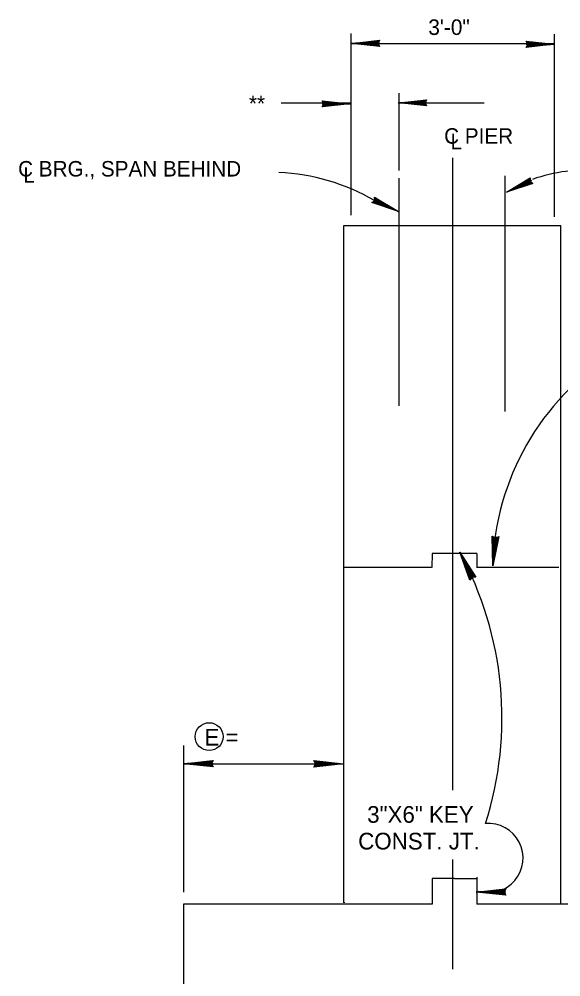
# Model space of a CAD drawing. Extents: x 1.6 to 6.29, y 2.8 to 7.08.
# Drawn here: x 3.826 to 4.232, y 5.231 to 5.949 of the extents above; entities that cross this region are included whole.
import ezdxf

# ---------------------------------------------------------------- set-up
doc = ezdxf.new("R2010")
doc.units = 0
doc.layers.add('Level 1', color=7, linetype='Continuous')
doc.layers.add('Level 5', color=7, linetype='Continuous')

msp = doc.modelspace()

# ---------------------------------------------------------------- linework, layer by layer
at = {"layer": 'Level 1'}
for p, q in [((4.07433, 5.93775), (4.07433, 5.80192)), ((4.07508, 5.93042), (4.09575, 5.93275)), ((4.09533, 5.93242), (4.081, 5.93083)), ((4.09533, 5.93217), (4.081, 5.93067)), ((4.09542, 5.932), (4.081, 5.93042)), ((4.09542, 5.93175), (4.081, 5.93017)), ((4.08408, 5.93017), (4.09475, 5.93142)), ((4.09475, 5.93142), (4.09433, 5.93017)), ((4.0945, 5.9305), (4.09483, 5.93142)), ((4.09575, 5.93275), (4.09475, 5.93042)), ((4.09483, 5.93142), (4.09533, 5.93242)), ((4.20567, 5.93208), (4.2265, 5.92983)), ((4.20675, 5.92983), (4.20567, 5.93208)), ((4.206, 5.93175), (4.22158, 5.93)), ((4.206, 5.93167), (4.22158, 5.92992)), ((4.206, 5.93158), (4.22158, 5.92992)), ((4.206, 5.93142), (4.22158, 5.92967)), ((4.20608, 5.93183), (4.22158, 5.93017)), ((4.20717, 5.92992), (4.20625, 5.93142)), ((4.20625, 5.93142), (4.20667, 5.93117)), ((4.22658, 5.93725), (4.22658, 5.80067)), ((4.0745, 5.93042), (4.2265, 5.93042)), ((4.09575, 5.93042), (4.07508, 5.93042)), ((4.09575, 5.92817), (4.07508, 5.93042)), ((4.08042, 5.93083), (4.07792, 5.93058)), ((4.07792, 5.93058), (4.09442, 5.93067)), ((4.0785, 5.93025), (4.08042, 5.93083)), ((4.08775, 5.92992), (4.0785, 5.93025)), ((4.09542, 5.92892), (4.08, 5.9305)), ((4.09533, 5.92867), (4.08, 5.93033)), ((4.09533, 5.92842), (4.08, 5.93017)), ((4.09533, 5.92842), (4.08, 5.93017)), ((4.09533, 5.92858), (4.08, 5.93017)), ((4.09467, 5.93092), (4.08408, 5.93017)), ((4.08517, 5.93), (4.08517, 5.93025)), ((4.08517, 5.93025), (4.087, 5.93017)), ((4.09442, 5.93017), (4.08517, 5.93)), ((4.087, 5.93017), (4.09442, 5.93)), ((4.09475, 5.92933), (4.08775, 5.92992)), ((4.09442, 5.93), (4.0885, 5.92992)), ((4.0885, 5.92992), (4.09467, 5.92967)), ((4.09442, 5.93067), (4.0895, 5.93092)), ((4.0895, 5.93092), (4.09467, 5.93092)), ((4.09467, 5.92967), (4.09025, 5.92958)), ((4.09025, 5.92958), (4.09475, 5.92933)), ((4.09433, 5.92992), (4.09375, 5.92967)), ((4.09375, 5.92967), (4.09417, 5.929)), ((4.09417, 5.929), (4.0945, 5.9305)), ((4.09433, 5.93017), (4.09517, 5.92875)), ((4.09475, 5.92908), (4.09433, 5.92992)), ((4.09475, 5.93042), (4.09575, 5.92817)), ((4.09517, 5.92875), (4.09475, 5.92908)), ((4.20567, 5.92983), (4.2265, 5.92983)), ((4.2265, 5.92983), (4.20567, 5.92742)), ((4.20567, 5.92742), (4.20675, 5.92983)), ((4.206, 5.92842), (4.2205, 5.93)), ((4.206, 5.92825), (4.2205, 5.92983)), ((4.206, 5.928), (4.22058, 5.92958)), ((4.20608, 5.92775), (4.22058, 5.92942)), ((4.2065, 5.92892), (4.20608, 5.92783)), ((4.20692, 5.92967), (4.2065, 5.92892)), ((4.21108, 5.93067), (4.20658, 5.93092)), ((4.20658, 5.93092), (4.21375, 5.93033)), ((4.20667, 5.93117), (4.20717, 5.93033)), ((4.21733, 5.92992), (4.20667, 5.92892)), ((4.20667, 5.92892), (4.20717, 5.92992)), ((4.20683, 5.9305), (4.21108, 5.93067)), ((4.21308, 5.93033), (4.20683, 5.9305)), ((4.20683, 5.92925), (4.21733, 5.92992)), ((4.21192, 5.92925), (4.20683, 5.92925)), ((4.20725, 5.93117), (4.20692, 5.92967)), ((4.207, 5.93017), (4.21308, 5.93033)), ((4.207, 5.93), (4.21633, 5.93017)), ((4.2145, 5.93), (4.207, 5.93017)), ((4.22375, 5.92967), (4.207, 5.92958)), ((4.207, 5.92958), (4.21192, 5.92925)), ((4.20717, 5.93033), (4.20758, 5.93058)), ((4.20758, 5.93058), (4.20725, 5.93117)), ((4.21375, 5.93033), (4.223, 5.92992)), ((4.21625, 5.92992), (4.2145, 5.93)), ((4.21633, 5.93017), (4.21625, 5.92992)), ((4.223, 5.92992), (4.22108, 5.92942)), ((4.22108, 5.92942), (4.22375, 5.92967)), ((4.11025, 5.89317), (4.11025, 5.83517)), ((4.02225, 5.88583), (4.07375, 5.88583)), ((4.05292, 5.8875), (4.07375, 5.88525)), ((4.054, 5.88525), (4.05292, 5.8875)), ((4.05292, 5.88525), (4.07375, 5.88525)), ((4.07375, 5.88525), (4.05292, 5.88283)), ((4.05292, 5.88283), (4.054, 5.88525)), ((4.05325, 5.88717), (4.06883, 5.88542)), ((4.05325, 5.88708), (4.06883, 5.88533)), ((4.05325, 5.887), (4.06883, 5.88533)), ((4.05325, 5.88683), (4.06883, 5.88508)), ((4.05325, 5.88383), (4.06775, 5.88542)), ((4.05325, 5.88367), (4.06775, 5.88525)), ((4.05325, 5.88342), (4.06783, 5.885)), ((4.05333, 5.88725), (4.06883, 5.88558)), ((4.05333, 5.88317), (4.06783, 5.88483)), ((4.05375, 5.88433), (4.05333, 5.88325)), ((4.05442, 5.88533), (4.0535, 5.88683)), ((4.0535, 5.88683), (4.05392, 5.88658)), ((4.05417, 5.88508), (4.05375, 5.88433)), ((4.05833, 5.88608), (4.05383, 5.88633)), ((4.05383, 5.88633), (4.061, 5.88575)), ((4.05392, 5.88658), (4.05442, 5.88575)), ((4.06458, 5.88533), (4.05392, 5.88433)), ((4.05392, 5.88433), (4.05442, 5.88533)), ((4.05408, 5.88592), (4.05833, 5.88608)), ((4.06033, 5.88575), (4.05408, 5.88592)), ((4.05408, 5.88467), (4.06458, 5.88533)), ((4.05917, 5.88467), (4.05408, 5.88467)), ((4.0545, 5.88658), (4.05417, 5.88508)), ((4.05425, 5.88558), (4.06033, 5.88575)), ((4.05425, 5.88542), (4.06358, 5.88558)), ((4.06175, 5.88542), (4.05425, 5.88558)), ((4.071, 5.88508), (4.05425, 5.885)), ((4.05425, 5.885), (4.05917, 5.88467)), ((4.05442, 5.88575), (4.05483, 5.886)), ((4.05483, 5.886), (4.0545, 5.88658)), ((4.061, 5.88575), (4.07025, 5.88533)), ((4.0635, 5.88533), (4.06175, 5.88542)), ((4.06358, 5.88558), (4.0635, 5.88533)), ((4.07025, 5.88533), (4.06833, 5.88483)), ((4.06833, 5.88483), (4.071, 5.88508)), ((4.10967, 5.88583), (4.17425, 5.88583)), ((4.11025, 5.88583), (4.13092, 5.88817)), ((4.13092, 5.88583), (4.11025, 5.88583)), ((4.13092, 5.88358), (4.11025, 5.88583)), ((4.11558, 5.88625), (4.11308, 5.886)), ((4.11308, 5.886), (4.12958, 5.88608)), ((4.11367, 5.88567), (4.11558, 5.88625)), ((4.12292, 5.88533), (4.11367, 5.88567)), ((4.13058, 5.88433), (4.11517, 5.88592)), ((4.1305, 5.88408), (4.11517, 5.88575)), ((4.1305, 5.88383), (4.11517, 5.88558)), ((4.1305, 5.88383), (4.11517, 5.88558)), ((4.1305, 5.884), (4.11517, 5.88558)), ((4.1305, 5.88783), (4.11617, 5.88625)), ((4.1305, 5.88758), (4.11617, 5.88608)), ((4.13058, 5.88742), (4.11617, 5.88583)), ((4.13058, 5.88717), (4.11617, 5.88558)), ((4.11925, 5.88558), (4.12992, 5.88683)), ((4.12983, 5.88633), (4.11925, 5.88558)), ((4.12033, 5.88542), (4.12033, 5.88567)), ((4.12033, 5.88567), (4.12217, 5.88558)), ((4.12958, 5.88558), (4.12033, 5.88542)), ((4.12217, 5.88558), (4.12958, 5.88542)), ((4.12992, 5.88475), (4.12292, 5.88533)), ((4.12958, 5.88542), (4.12367, 5.88533)), ((4.12367, 5.88533), (4.12983, 5.88508)), ((4.12958, 5.88608), (4.12467, 5.88633)), ((4.12467, 5.88633), (4.12983, 5.88633)), ((4.12983, 5.88508), (4.12542, 5.885)), ((4.12542, 5.885), (4.12992, 5.88475)), ((4.1295, 5.88533), (4.12892, 5.88508)), ((4.12892, 5.88508), (4.12933, 5.88442)), ((4.12933, 5.88442), (4.12967, 5.88592)), ((4.12992, 5.88683), (4.1295, 5.88558)), ((4.1295, 5.88558), (4.13033, 5.88417)), ((4.12992, 5.8845), (4.1295, 5.88533)), ((4.12967, 5.88592), (4.13, 5.88683)), ((4.13092, 5.88817), (4.12992, 5.88583)), ((4.12992, 5.88583), (4.13092, 5.88358)), ((4.13033, 5.88417), (4.12992, 5.8845)), ((4.13, 5.88683), (4.1305, 5.88783)), ((4.1895, 5.83133), (4.1895, 5.65483)), ((4.11033, 5.8295), (4.11033, 5.65892)), ((4.19075, 5.81892), (4.2085, 5.82983)), ((4.2095, 5.82767), (4.19075, 5.81892)), ((4.2105, 5.82558), (4.19075, 5.81892)), ((4.19325, 5.82033), (4.20817, 5.82733)), ((4.2025, 5.82392), (4.19392, 5.82033)), ((4.20983, 5.82617), (4.19525, 5.82117)), ((4.21, 5.82592), (4.19525, 5.82083)), ((4.20983, 5.82583), (4.19525, 5.82092)), ((4.20983, 5.82575), (4.19525, 5.82083)), ((4.21, 5.82567), (4.19533, 5.82075)), ((4.20825, 5.82925), (4.19592, 5.82183)), ((4.20842, 5.82917), (4.196, 5.82158)), ((4.2085, 5.82892), (4.19608, 5.82142)), ((4.20858, 5.82867), (4.19625, 5.82117)), ((4.199, 5.8225), (4.20817, 5.82808)), ((4.20825, 5.82775), (4.199, 5.8225)), ((4.20825, 5.827), (4.2, 5.82292)), ((4.20158, 5.82375), (4.20842, 5.82675)), ((4.20917, 5.82642), (4.2025, 5.82392)), ((4.20842, 5.82675), (4.20317, 5.82408)), ((4.20317, 5.82408), (4.20875, 5.82658)), ((4.20358, 5.82558), (4.20825, 5.82775)), ((4.20817, 5.82733), (4.20358, 5.82558)), ((4.20875, 5.82658), (4.20483, 5.82458)), ((4.20483, 5.82458), (4.20917, 5.82642)), ((4.20842, 5.8265), (4.20808, 5.82617)), ((4.20808, 5.82617), (4.20875, 5.82575)), ((4.20817, 5.82808), (4.20825, 5.82683)), ((4.20825, 5.82817), (4.20825, 5.82925)), ((4.20825, 5.82717), (4.20825, 5.82817)), ((4.20875, 5.82575), (4.20825, 5.82717)), ((4.20825, 5.82683), (4.20967, 5.82592)), ((4.20908, 5.82592), (4.20842, 5.8265)), ((4.2085, 5.82983), (4.2085, 5.82717)), ((4.2085, 5.82717), (4.2105, 5.82558)), ((4.20967, 5.82592), (4.20908, 5.82592)), ((4.1955, 5.8215), (4.19325, 5.82033)), ((4.19392, 5.82033), (4.1955, 5.8215)), ((4.2, 5.823), (4.20158, 5.82375)), ((4.2, 5.82292), (4.2, 5.823)), ((4.09017, 5.81117), (4.09225, 5.81275)), ((4.11008, 5.80442), (4.09017, 5.81117)), ((4.09158, 5.812), (4.09075, 5.81125)), ((4.09075, 5.81142), (4.10467, 5.80675)), ((4.09075, 5.81117), (4.1045, 5.80658)), ((4.09092, 5.81167), (4.10467, 5.807)), ((4.091, 5.81192), (4.10475, 5.80717)), ((4.09125, 5.81325), (4.11008, 5.80442)), ((4.09225, 5.81267), (4.09158, 5.812)), ((4.09175, 5.812), (4.09258, 5.81275)), ((4.10192, 5.80842), (4.09175, 5.812)), ((4.09667, 5.81017), (4.092, 5.81217)), ((4.092, 5.81217), (4.10192, 5.80842)), ((4.09217, 5.81525), (4.11008, 5.80442)), ((4.09225, 5.81275), (4.09217, 5.81525)), ((4.09225, 5.81467), (4.10567, 5.80658)), ((4.09225, 5.8145), (4.10558, 5.80642)), ((4.09325, 5.81392), (4.09225, 5.81267)), ((4.09233, 5.81492), (4.10575, 5.80667)), ((4.09233, 5.81483), (4.10575, 5.80667)), ((4.09258, 5.81275), (4.09233, 5.8145)), ((4.09233, 5.8145), (4.09267, 5.814)), ((4.1075, 5.8055), (4.09233, 5.81242)), ((4.09233, 5.81242), (4.09667, 5.81017)), ((4.0925, 5.81492), (4.10575, 5.80675)), ((4.0965, 5.81167), (4.0925, 5.81392)), ((4.0925, 5.81392), (4.09875, 5.81025)), ((4.09817, 5.81058), (4.09258, 5.81342)), ((4.09258, 5.81342), (4.0965, 5.81167)), ((4.09258, 5.81283), (4.101, 5.80908)), ((4.09267, 5.814), (4.09275, 5.81308)), ((4.09942, 5.80967), (4.09267, 5.813)), ((4.09267, 5.813), (4.09817, 5.81058)), ((4.09275, 5.81308), (4.09325, 5.81308)), ((4.09325, 5.81308), (4.09325, 5.81392)), ((4.09875, 5.81025), (4.107, 5.80608)), ((4.10092, 5.80892), (4.09942, 5.80967)), ((4.101, 5.80908), (4.10092, 5.80892)), ((4.107, 5.80608), (4.105, 5.80642)), ((4.105, 5.80642), (4.1075, 5.8055)), ((4.06908, 5.28692), (4.06908, 5.79417)), ((4.06908, 5.79417), (4.2315, 5.79417)), ((4.2315, 5.28625), (4.2315, 5.79417)), ((4.18067, 5.53925), (4.18017, 5.5615)), ((4.18017, 5.5615), (4.18258, 5.56008)), ((4.18042, 5.56108), (4.18083, 5.54558)), ((4.1815, 5.5605), (4.1805, 5.56108)), ((4.18258, 5.56125), (4.18067, 5.53925)), ((4.18508, 5.56108), (4.18067, 5.53925)), ((4.18067, 5.561), (4.181, 5.5455)), ((4.18083, 5.54225), (4.18225, 5.55983)), ((4.18092, 5.561), (4.18125, 5.54558)), ((4.18425, 5.56075), (4.18108, 5.5445)), ((4.18117, 5.561), (4.18158, 5.54567)), ((4.18442, 5.56075), (4.18117, 5.5445)), ((4.18458, 5.56067), (4.18142, 5.54442)), ((4.18475, 5.56067), (4.1815, 5.54442)), ((4.18467, 5.56067), (4.1815, 5.54442)), ((4.18242, 5.55992), (4.1815, 5.5605)), ((4.18183, 5.54883), (4.1815, 5.56033)), ((4.1815, 5.56033), (4.18275, 5.55967)), ((4.1815, 5.55475), (4.182, 5.56017)), ((4.18225, 5.55983), (4.1815, 5.55475)), ((4.182, 5.56017), (4.18183, 5.54883)), ((4.18283, 5.55975), (4.182, 5.55)), ((4.18217, 5.55183), (4.18283, 5.55975)), ((4.184, 5.55942), (4.18242, 5.55992)), ((4.18367, 5.56017), (4.1825, 5.55267)), ((4.18258, 5.56008), (4.18508, 5.56108)), ((4.18267, 5.55342), (4.18317, 5.56008)), ((4.18283, 5.55975), (4.18267, 5.55342)), ((4.18275, 5.55967), (4.18433, 5.56058)), ((4.183, 5.55542), (4.18367, 5.56017)), ((4.18317, 5.56008), (4.183, 5.55542)), ((4.184, 5.56008), (4.18308, 5.55967)), ((4.18308, 5.55967), (4.18325, 5.55917)), ((4.18325, 5.55917), (4.184, 5.55942)), ((4.18433, 5.56058), (4.184, 5.56008)), ((4.1825, 5.55267), (4.18108, 5.54292)), ((4.18175, 5.55008), (4.18217, 5.55183)), ((4.13525, 5.54833), (4.135, 5.53783)), ((4.16867, 5.54833), (4.13525, 5.54833)), ((4.16575, 5.5295), (4.15583, 5.54942)), ((4.16333, 5.52842), (4.15583, 5.54942)), ((4.15583, 5.54942), (4.16792, 5.53075)), ((4.15875, 5.5445), (4.15725, 5.54692)), ((4.15725, 5.54692), (4.16508, 5.53108)), ((4.16133, 5.53708), (4.15742, 5.54608)), ((4.15742, 5.54608), (4.15875, 5.5445)), ((4.1635, 5.529), (4.15783, 5.54458)), ((4.16358, 5.52892), (4.15792, 5.54458)), ((4.16367, 5.52892), (4.158, 5.54483)), ((4.16383, 5.529), (4.158, 5.54475)), ((4.16392, 5.52908), (4.15817, 5.54483)), ((4.16867, 5.54833), (4.16867, 5.53775)), ((4.18108, 5.54292), (4.18083, 5.54508)), ((4.18083, 5.54508), (4.18083, 5.54225)), ((4.182, 5.55), (4.18175, 5.55008)), ((4.13483, 5.53792), (4.069, 5.53792)), ((4.16683, 5.5305), (4.15842, 5.54367)), ((4.167, 5.53067), (4.15858, 5.54392)), ((4.16717, 5.53075), (4.15883, 5.54392)), ((4.16733, 5.53083), (4.159, 5.54392)), ((4.1655, 5.53083), (4.16, 5.54058)), ((4.16, 5.54058), (4.16617, 5.53092)), ((4.16025, 5.5395), (4.1605, 5.53967)), ((4.16475, 5.53075), (4.16025, 5.5395)), ((4.1605, 5.53967), (4.16117, 5.53783)), ((4.16117, 5.53783), (4.16458, 5.53058)), ((4.16425, 5.52975), (4.16133, 5.53708)), ((4.23, 5.53792), (4.16858, 5.53792)), ((4.16458, 5.53058), (4.16142, 5.53642)), ((4.16142, 5.53642), (4.1645, 5.53025)), ((4.1645, 5.53025), (4.16233, 5.5345)), ((4.16233, 5.5345), (4.16425, 5.52975)), ((4.16508, 5.53108), (4.16308, 5.53575)), ((4.16308, 5.53575), (4.1655, 5.53083)), ((4.16525, 5.53067), (4.16333, 5.52842)), ((4.164, 5.53108), (4.16358, 5.53042)), ((4.16358, 5.53042), (4.16517, 5.53075)), ((4.16483, 5.53092), (4.16383, 5.52917)), ((4.16383, 5.52917), (4.16392, 5.52992)), ((4.16392, 5.52992), (4.16442, 5.53058)), ((4.16442, 5.53058), (4.164, 5.53108)), ((4.16617, 5.53092), (4.16483, 5.53092)), ((4.16517, 5.53075), (4.16617, 5.53083)), ((4.16792, 5.53075), (4.16525, 5.53067)), ((4.16617, 5.53083), (4.16725, 5.531)), ((3.94908, 5.40475), (3.94908, 5.30458)), ((3.94917, 5.391), (3.97125, 5.3935)), ((3.97125, 5.3935), (3.97008, 5.391)), ((3.97125, 5.391), (3.94917, 5.391)), ((3.97125, 5.38858), (3.94917, 5.391)), ((3.94975, 5.391), (4.066, 5.391)), ((3.95483, 5.39142), (3.95217, 5.39117)), ((3.95217, 5.39117), (3.96975, 5.39125)), ((3.95283, 5.39083), (3.95483, 5.39142)), ((3.96267, 5.39042), (3.95283, 5.39083)), ((3.97075, 5.38892), (3.95433, 5.39075)), ((3.97075, 5.389), (3.95433, 5.39075)), ((3.97075, 5.38883), (3.95433, 5.39067)), ((3.97083, 5.38933), (3.95442, 5.39108)), ((3.97075, 5.38908), (3.95442, 5.39092)), ((3.97075, 5.39308), (3.95542, 5.39142)), ((3.97075, 5.39292), (3.95542, 5.39125)), ((3.97083, 5.39267), (3.9555, 5.391)), ((3.97083, 5.39242), (3.9555, 5.39075)), ((3.95875, 5.39075), (3.97008, 5.392)), ((3.97, 5.39158), (3.95875, 5.39075)), ((3.95992, 5.39058), (3.95992, 5.39083)), ((3.95992, 5.39083), (3.96183, 5.39075)), ((3.96975, 5.39075), (3.95992, 5.39058)), ((3.96183, 5.39075), (3.96975, 5.39058)), ((3.97017, 5.38983), (3.96267, 5.39042)), ((3.96975, 5.39058), (3.96342, 5.39042)), ((3.96342, 5.39042), (3.97, 5.39025)), ((3.96975, 5.39125), (3.96458, 5.39158)), ((3.96458, 5.39158), (3.97, 5.39158)), ((3.97, 5.39025), (3.96533, 5.39008)), ((3.96533, 5.39008), (3.97017, 5.38983)), ((3.96967, 5.39042), (3.96908, 5.39017)), ((3.96908, 5.39017), (3.9695, 5.3895)), ((3.9695, 5.3895), (3.96983, 5.39108)), ((3.97008, 5.392), (3.96967, 5.39075)), ((3.96967, 5.39075), (3.97058, 5.38925)), ((3.97008, 5.38958), (3.96967, 5.39042)), ((3.96983, 5.39108), (3.97025, 5.392)), ((3.97008, 5.391), (3.97125, 5.38858)), ((3.97058, 5.38925), (3.97008, 5.38958)), ((3.97025, 5.392), (3.97075, 5.39308)), ((4.04667, 5.39342), (4.06892, 5.391)), ((4.04783, 5.391), (4.04667, 5.39342)), ((4.04667, 5.391), (4.06892, 5.391)), ((4.06892, 5.391), (4.04667, 5.3885)), ((4.04667, 5.3885), (4.04783, 5.391)), ((4.047, 5.38958), (4.0625, 5.39125)), ((4.04708, 5.39308), (4.06367, 5.39125)), ((4.04708, 5.393), (4.06367, 5.39117)), ((4.04708, 5.39292), (4.06367, 5.39108)), ((4.04708, 5.39267), (4.06367, 5.39083)), ((4.04708, 5.38933), (4.0625, 5.391)), ((4.04708, 5.38908), (4.06258, 5.39075)), ((4.04717, 5.39317), (4.06367, 5.39133)), ((4.04717, 5.38883), (4.06258, 5.39058)), ((4.04758, 5.39), (4.04717, 5.38892)), ((4.04825, 5.39117), (4.04725, 5.39275)), ((4.04725, 5.39275), (4.04775, 5.39242)), ((4.048, 5.39092), (4.04758, 5.39)), ((4.0525, 5.39192), (4.04767, 5.39217)), ((4.04767, 5.39217), (4.05533, 5.39158)), ((4.04775, 5.39242), (4.04825, 5.39158)), ((4.05917, 5.39117), (4.04775, 5.39)), ((4.04775, 5.39), (4.04825, 5.39117)), ((4.04792, 5.39175), (4.0525, 5.39192)), ((4.05458, 5.39158), (4.04792, 5.39175)), ((4.04792, 5.39042), (4.05917, 5.39117)), ((4.05333, 5.39042), (4.04792, 5.39042)), ((4.04833, 5.3925), (4.048, 5.39092)), ((4.04817, 5.39142), (4.05458, 5.39158)), ((4.04817, 5.39125), (4.05808, 5.39142)), ((4.05617, 5.39125), (4.04817, 5.39142)), ((4.06592, 5.39083), (4.04817, 5.39075)), ((4.04817, 5.39075), (4.05333, 5.39042)), ((4.04825, 5.39158), (4.04875, 5.39183)), ((4.04875, 5.39183), (4.04833, 5.3925)), ((4.05533, 5.39158), (4.06517, 5.39117)), ((4.058, 5.39117), (4.05617, 5.39125)), ((4.05808, 5.39142), (4.058, 5.39117)), ((4.06517, 5.39117), (4.06317, 5.39058)), ((4.06317, 5.39058), (4.06592, 5.39083)), ((3.94908, 5.30458), (3.94908, 5.29467)), ((4.15192, 5.305), (4.13525, 5.305)), ((4.13525, 5.305), (4.13525, 5.28592)), ((4.15192, 5.305), (4.16858, 5.305)), ((4.16858, 5.30592), (4.16858, 5.28592)), ((4.16817, 5.29483), (4.19025, 5.29733)), ((4.19025, 5.29483), (4.16817, 5.29483)), ((4.19025, 5.29242), (4.16817, 5.29483)), ((4.17383, 5.29525), (4.17117, 5.295)), ((4.17117, 5.295), (4.18875, 5.29508)), ((4.17183, 5.29467), (4.17383, 5.29525)), ((4.18167, 5.29425), (4.17183, 5.29467)), ((4.18975, 5.29275), (4.17333, 5.29458)), ((4.18975, 5.29283), (4.17333, 5.29458)), ((4.18975, 5.29267), (4.17333, 5.2945)), ((4.18983, 5.29317), (4.17342, 5.29492)), ((4.18975, 5.29292), (4.17342, 5.29475)), ((4.18975, 5.29692), (4.17442, 5.29525)), ((4.18975, 5.29675), (4.17442, 5.29508)), ((4.18983, 5.2965), (4.1745, 5.29483)), ((4.18983, 5.29625), (4.1745, 5.29458)), ((4.17775, 5.29458), (4.18908, 5.29583)), ((4.189, 5.29542), (4.17775, 5.29458)), ((4.17892, 5.29442), (4.17892, 5.29467)), ((4.17892, 5.29467), (4.18083, 5.29458)), ((4.18875, 5.29458), (4.17892, 5.29442)), ((4.18083, 5.29458), (4.18875, 5.29442)), ((4.18917, 5.29367), (4.18167, 5.29425)), ((4.18875, 5.29442), (4.18242, 5.29425)), ((4.18242, 5.29425), (4.189, 5.29408)), ((4.18875, 5.29508), (4.18358, 5.29542)), ((4.18358, 5.29542), (4.189, 5.29542)), ((4.189, 5.29408), (4.18433, 5.29392)), ((4.18433, 5.29392), (4.18917, 5.29367)), ((4.18867, 5.29425), (4.18808, 5.294)), ((4.18808, 5.294), (4.1885, 5.29333)), ((4.1885, 5.29333), (4.18883, 5.29492)), ((4.18908, 5.29583), (4.18867, 5.29458)), ((4.18867, 5.29458), (4.18958, 5.29308)), ((4.18908, 5.29342), (4.18867, 5.29425)), ((4.18883, 5.29492), (4.18925, 5.29583)), ((4.19025, 5.29733), (4.18908, 5.29483)), ((4.18908, 5.29483), (4.19025, 5.29242)), ((4.18958, 5.29308), (4.18908, 5.29342)), ((4.18925, 5.29583), (4.18975, 5.29692)), ((3.94917, 5.286), (4.13525, 5.286)), ((3.94917, 5.28592), (3.94917, 5.13467)), ((4.06925, 5.28733), (4.06925, 5.28683)), ((4.16858, 5.286), (4.35417, 5.286))]:
    msp.add_line(p, q, dxfattribs=at)
msp.add_circle((3.96827, 5.41129), 0.01042, dxfattribs=at)
for centre, radius, start, end in [((4.25019, 5.71746), 0.11807, 84.66253, 109.74805), ((4.37292, 5.5346), 0.19231, 122.06338, 178.61588)]:
    msp.add_arc(centre, radius, start, end, dxfattribs=at)
at = {"layer": 'Level 5'}
for p, q in [((4.15033, 5.84467), (4.15033, 5.37117)), ((4.15033, 5.84467), (4.15033, 5.64483)), ((4.15033, 5.31925), (4.15033, 5.23717))]:
    msp.add_line(p, q, dxfattribs=at)
for centre, radius, start, end in [((4.01383, 5.67875), 0.15509, 59.71776, 87.51672), ((3.92857, 5.42536), 0.25892, 342.19097, 28.62983), ((4.17727, 5.32027), 0.02599, 252.403, 94.83388)]:
    msp.add_arc(centre, radius, start, end, dxfattribs=at)

# ---------------------------------------------------------------- texts
at = {"layer": 'Level 1'}
for s, height, p in [('3\'-0"', 0.011667, (4.13233, 5.93675)), ('**', 0.011666, (3.998, 5.87958)), ('C PIER', 0.011584, (4.14417, 5.85533)), ('L', 0.01158, (4.14892, 5.85117)), ('C BRG., SPAN BEHIND', 0.0115835, (3.82525, 5.83075)), ('L', 0.01158, (3.82908, 5.82608))]:
    msp.add_text(s, height=height, dxfattribs=at).set_placement(p)
at = {"layer": 'Level 5'}
for s, p in [('E =      ', (3.96467, 5.40458)), ('3"X6" KEY', (4.08658, 5.34675)), ('CONST. JT.', (4.07983, 5.32675))]:
    msp.add_text(s, height=0.0125, dxfattribs=at).set_placement(p)

doc.saveas('drawing.dxf')
